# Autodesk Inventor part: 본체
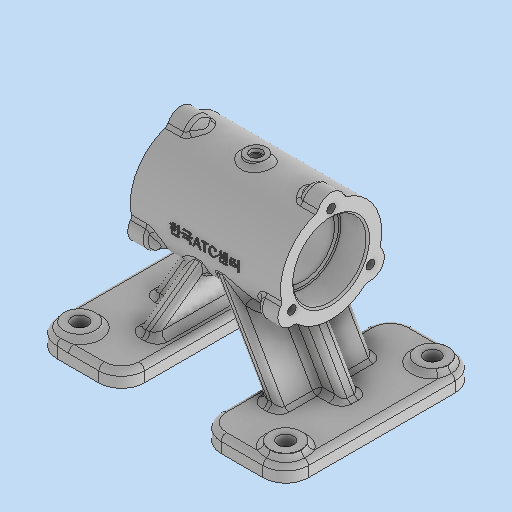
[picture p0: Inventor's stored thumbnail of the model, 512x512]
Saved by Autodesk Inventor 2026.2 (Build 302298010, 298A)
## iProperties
Created: 2026-04
Part Number: 본체
Material: 일반
Document SubType Name: Modeling
Designer: PC-2-03
Density: 1 g/cm^3
Appearance: 기본값
Author: PC-2-03
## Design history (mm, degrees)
sketch "스케치1"
  geometry: L1 (-72, 55)-(72, 55); L2 (72, 55)-(72, -55); L3 (72, -55)-(-72, -55); L4 (-72, -55)-(-72, 55); 3 further points
  constraints: 8 end point, 2 midpoint, 2 parallel, 1 horizontal, 1 horizontal alignment, 1 perpendicular, 1 vertical alignment
  dimensions: "d0" = 144 distance between parallel lines of L4 L2; "d1" = 110 distance of L1.end L2.end
extrude "돌출1" new body sketch "스케치1" distance "d2" = 9; taper "d3" = 0 deg
sketch "스케치2"
  geometry: L1 (72, 55)-(-72, 55) reference; L2 (-22, -55)-(22, -55); L3 (22, -55)-(22, 55); L4 (22, 55)-(-22, 55); L5 (-22, 55)-(-22, -55); L6 (-22, -55)-(22, 55); L7 (22, -55)-(-22, 55); 2 further points
  constraints: 12 end point, 2 midpoint, 2 parallel, 1 horizontal, 1 perpendicular, 1 point on line
  dimensions: "d4" = 44 distance between parallel lines of L3 L5
extrude "돌출2" cut sketch "스케치2" extent not by distance; stored distance "d5" = 0; taper "d6" = 0 deg
sketch "스케치3"
  geometry: L1 (-55, 0)-(55, 0) reference; L2 (55, 0)-(55, 9) reference; C1 r 29 at (0, 72); 1 further point
  constraints: 1 centre point
  dimensions: "d7" = 58 diameter of C1; "d8" = 72 distance from line of L1 C1.centre; "d9" = 55 distance from line of C1.centre L2
extrude "돌출3" join sketch "스케치3" stored distance "d10" = 86; taper "d11" = 0 deg
sketch "스케치4"
  geometry: L1 (22, 9)-(72, 9) reference; L2 (43, 43)-(-43, 43) reference; L3 (0, 64.426)-(-32, 9); L4 (-72, 9)-(-22, 9) reference; L5 (-4.865, 72)-(-41.238, 9); L6 (4.865, 72)-(41.238, 9); L7 (0, 43)-(0, 21.006); L8 (32, 9)-(-1.549, 67.108); L9 (6.618, 75.888)-(-0.31, 79.888); L10 (43, 43)-(43, 101) reference; L11 (43, 72)-(4.865, 72); L12 (-4.865, 72)-(-43, 72); L13 (4.865, 72)-(-4.865, 72); 3 further points
  constraints: 18 end point, 7 point on line, 3 horizontal, 2 midpoint, 2 parallel, 1 perpendicular, 1 vertical
  dimensions: "d13" = 8 distance from line of L3 point (-33.577, 22.269); "d14" = 30 deg angle of L7 L3 (= 0.5 x d12); "d15" = 10 distance of L4.end L3.end; "d18" = 60 deg angle of L3 L8; "d19" = 8 distance between parallel lines of L8 L6; "d20" = 10 distance of L1.start L8.start; "d21" = 81.85451 distance of L9.end L5.end
extrude "돌출4" join sketch "스케치4" stored distance "d22" = 54; taper "d23" = 0 deg
sketch "스케치5" dims "d156" = 52
  geometry: A1 r 29 centre (0, 0) between (-27.942, -7.761) and (-27.942, 7.761) reference; A2 r 8 centre (-26, 0) between (-27.942, 7.761) and (-27.942, -7.761); 2 further points
  constraints: 4 point on circle, 2 horizontal alignment, 1 centre point, 3 other
  dimensions: "d157" = 8 radius of A2
extrude "돌출5" join sketch "스케치5" distance "d25" = 10; taper "d26" = 0 deg
sketch "스케치6" dims "d161" = 52
  geometry: A1 r 29 centre (0, 0) between (27.942, 7.761) and (27.942, -7.761) reference; A2 r 8 centre (26, 0) between (27.942, -7.761) and (27.942, 7.761); 2 further points
  constraints: 4 point on circle, 2 horizontal alignment, 1 centre point, 3 other
  dimensions: "d162" = 8 radius of A2
extrude "돌출6" join sketch "스케치6" distance "d31" = 10; taper "d32" = 0 deg
node "작업 평면1"
sketch "스케치7"
  geometry: C1 r 6 at (0, 0); 1 further point
  constraints: 1 centre point, 1 coincident
  dimensions: "d37" = 12 diameter of C1
extrude "돌출7" join sketch "스케치7" stored distance "d38" = 10; taper "d39" = 0 deg
node "작업 평면2"
sketch "스케치8"
  geometry: C1 r 6 at (0, 0); 1 further point
  constraints: 1 centre point, 1 coincident
  dimensions: "d41" = 12 diameter of C1
extrude "돌출8" join sketch "스케치8" stored distance "d42" = 10; taper "d43" = 0 deg
sketch "스케치11"
  geometry: C1 r 6 at (0, 0) reference; 2 further points
  constraints: 1 coincident
hole "구멍3" sketch "스케치11" at (0, 0) diameter "d58" = 5.1881; stored, may be unused: countersink angle "d62" = 90 deg, drill point angle "d64" = 0 deg; dims "d59" = 12, "d60" = 7, "d61" = 2, "d63" = 102.4
sketch "스케치12"
  geometry: C1 r 6 at (0, 0) reference; 2 further points
  constraints: 1 coincident
hole "구멍4" sketch "스케치12" at (0, 0) diameter "d65" = 7; stored, may be unused: countersink angle "d69" = 90 deg, drill point angle "d71" = 0 deg; dims "d66" = 12, "d67" = 7, "d68" = 2, "d70" = 2
sketch "스케치13"
  geometry: L1 (-72, 9)-(-22, 9) reference; L2 (-55.094, 9)-(-44.568, 27.231); L3 (-10.975, 61.417)-(-41.238, 9) reference; 1 further point
  constraints: 2 end point, 1 parallel, 1 point on line
  dimensions: "d72" = 12 distance between parallel lines of L3 L2
feature "리브1" sketch "스케치13" dims "d73" = 1, "d74" = 10, "d75" = 0, "d76" = 0, "d77" = 1, "d78" = 1
sketch "스케치14"
  geometry: L1 (22, 9)-(72, 9) reference; L2 (55.094, 9)-(49.718, 18.312); L3 (41.238, 9)-(10.975, 61.417) reference; 1 further point
  constraints: 2 end point, 1 parallel, 1 point on line
  dimensions: "d79" = 12 distance between parallel lines of L2 L3
feature "리브2" sketch "스케치14" dims "d80" = 1, "d81" = 10, "d82" = 0, "d83" = 0, "d84" = 1, "d85" = 1
sketch "스케치15"
  geometry: L1 (43, 98)-(25, 98); L2 (33, 106)-(33, 99.942) reference; L3 (25, 98)-(33, 106); L4 (43, 64.75)-(43, 99.942) reference; L5 (33, 106)-(33, 98); 3 further points
  constraints: 6 end point, 1 horizontal, 1 point on line, 1 vertical
  dimensions: "d163" = 45 deg angle of L3 L1; "d164" = 8 distance from line of L2.start L1
revolve "회전1" sketch "스케치15" stored, may be unused: angle "d87" = 360 deg
sketch "스케치16"
  geometry: L1 (-43, 106)-(-33, 106) reference; L2 (-33, 99.942)-(-33, 106) reference; L3 (-25, 98)-(-33, 106); L4 (-25, 98)-(-43, 98); L5 (-33, 106)-(-33, 98); 4 further points
  constraints: 6 end point, 2 point on line, 1 horizontal, 1 midpoint
  dimensions: "d159" = 16 diameter of L1 L4; "d160" = 45 deg angle of L4 L3
revolve "회전2" sketch "스케치16" stored, may be unused: angle "d92" = 360 deg
fillet "모깎기1" dims "d96" = 13
sketch "스케치17"
  geometry: C1 r 9 at (59, 42); A1 r 13 centre (59, 42) between (72, 42) and (59, 55) reference; 1 further point
  constraints: 1 centre point, 1 concentric
  dimensions: "d97" = 18 diameter of C1
extrude "돌출9" join sketch "스케치17" distance "d98" = 3; taper "d99" = 0 deg
sketch "스케치18"
  geometry: C1 r 9 at (0, 0) reference; 2 further points
  constraints: 1 coincident
hole "구멍5" sketch "스케치18" at (0, 0) diameter "d100" = 9; stored, may be unused: countersink angle "d104" = 90 deg, drill point angle "d106" = 0 deg; dims "d101" = 6, "d102" = 4, "d103" = 2, "d105" = 2
sketch "스케치19" dims "d113" = 52
  geometry: A1 r 29 centre (-72, 0) between (-99.942, -7.761) and (-64.75, -28.079) reference; A2 r 29 centre (-72, 0) between (-99.942, -7.761) and (-64.75, -28.079) reference; 7 further points
  constraints: 2 horizontal alignment, 1 coincident, 3 other
hole "구멍6" sketch "스케치19" at (-98, 0) diameter "d114" = 4.917; stored, may be unused: countersink angle "d118" = 90 deg, drill point angle "d120" = 118 deg; dims "d115" = 8, "d116" = 4, "d117" = 2, "d119" = 10
sketch "스케치9"
  geometry: A1 r 29 centre (-72, 0) between (-99.942, -7.761) and (-64.75, -28.079) reference; 4 further points
  constraints: 1 coincident
hole "구멍1" sketch "스케치9" at (-72, 0) diameter "d44" = 36; stored, may be unused: countersink angle "d48" = 90 deg, drill point angle "d50" = 0 deg; dims "d45" = 8, "d46" = 42, "d47" = 16, "d49" = 10
sketch "스케치10"
  geometry: C1 r 18 at (72, 0) reference; 2 further points
  constraints: 1 coincident
hole "구멍2" sketch "스케치10" at (72, 0) diameter "d51" = 42; stored, may be unused: countersink angle "d55" = 90 deg, drill point angle "d57" = 0 deg; dims "d52" = 6, "d53" = 42, "d54" = 16, "d56" = 16
sketch "스케치20" dims "d124" = 52
  geometry: A1 r 29 centre (72, 0) between (99.942, 7.761) and (64.75, 28.079) reference; 5 further points
  constraints: 2 horizontal alignment, 3 other
hole "구멍7" sketch "스케치20" at (98, 0) diameter "d125" = 4.917; stored, may be unused: countersink angle "d129" = 90 deg, drill point angle "d131" = 118 deg; dims "d126" = 8, "d127" = 4, "d128" = 2, "d130" = 10
fillet "모깎기2" dims "d135" = 3
fillet "모깎기3" dims "d136" = 3
fillet "모깎기15" dims "d170" = 3
fillet "모깎기4" dims "d137" = 3
fillet "모깎기7" dims "d140" = 3
chamfer "모따기1" distance "d143" = 1; stored, may be unused: second distance "d144" = 2, angle "d145" = 45 deg
fillet "모깎기10" dims "d146" = 3
fillet "모깎기11" dims "d147" = 0.6
node "작업 평면3"
sketch "스케치21"
  geometry: L1 (20, 5)-(-20, 5); L2 (-20, 5)-(-20, -5); L3 (-20, -5)-(20, -5); L4 (20, -5)-(20, 5); L5 (-20, 0)-(20, 0); L6 (0, -5)-(0, 5); L7 (-35, 72)-(-59, 72) reference; L8 (-43, 7.25)-(-43, -27.942) reference; 1 further point
  constraints: 4 end point, 4 midpoint, 2 other
  dimensions: "d149" = 10 distance between parallel lines of L1 L3; "d150" = 40 distance of L2.end L3.end; "d151" = 72 distance between parallel lines of L7 L5; "d152" = 43 distance between parallel lines of L8 L6
feature "엠보싱1" sketch "스케치21" dims "d153" = 0.5, "d154" = 0
fillet "모깎기12" dims "d155" = 3
fillet "모깎기13" dims "d165" = 3
fillet "모깎기14" dims "d166" = 3
node "솔리드1"
pattern_circular "원형 패턴1" dims angle "d28" = 360 deg
pattern_circular "원형 패턴2" dims angle "d34" = 360 deg
pattern_circular "원형 패턴3" dims angle "d89" = 360 deg
pattern_circular "원형 패턴4" dims angle "d94" = 360 deg
pattern_linear "직사각형 패턴1" dims "d112" = 84, "d169" = 118
pattern_circular "원형 패턴5" dims angle "d122" = 360 deg
pattern_circular "원형 패턴6" dims angle "d133" = 360 deg
feature "A9D066F2-1C7D-4E18-AEED-F7BC21143FA4" dims "d65" = 7, "d66" = 12, "d67" = 7, "d68" = 2, "d69" = 90 deg, "d70" = 2, "d71" = 0
other parameters: "d12" = 60 deg, "d36" = 104
